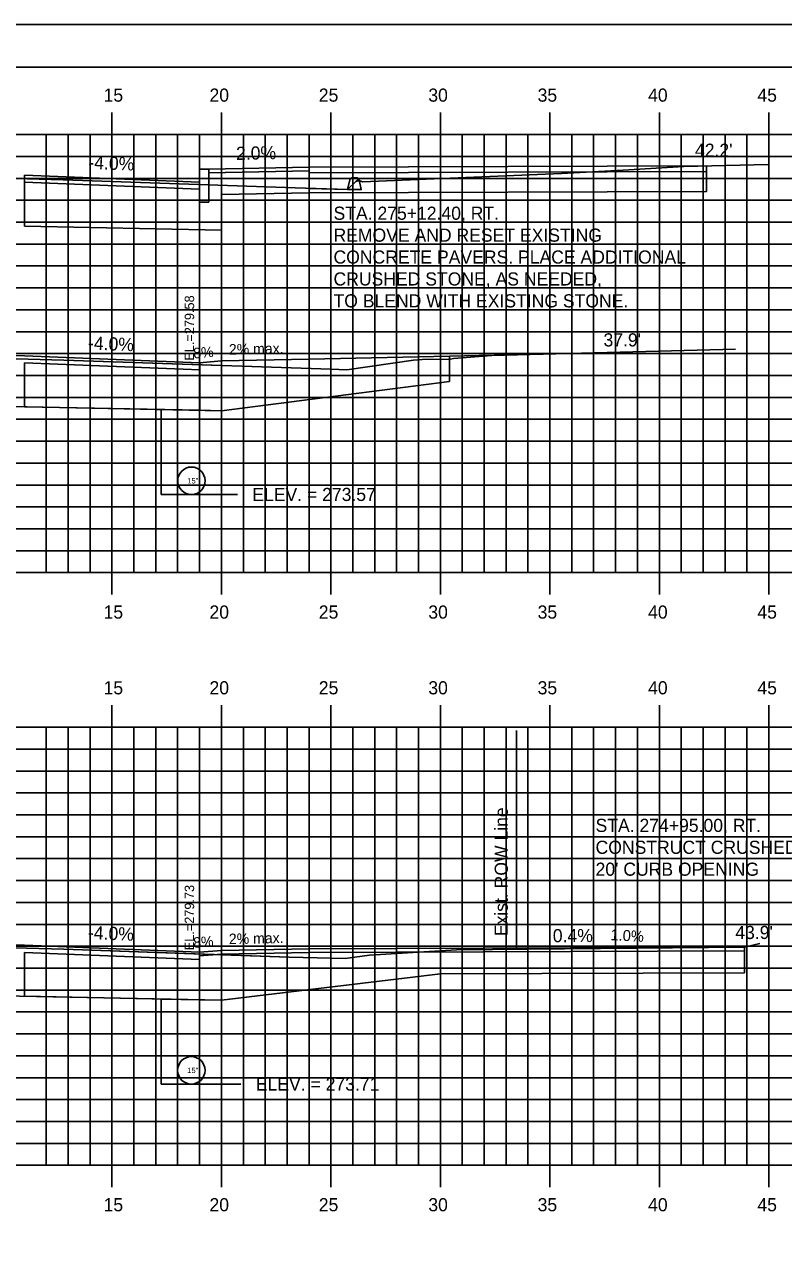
# Model space of a CAD drawing. Extents: x 853340 to 853510, y 366268 to 366378.
# Drawn here: x 853434.1 to 853468.8, y 366322.1 to 366378.2 of the extents above; entities that cross this region are included whole.
import ezdxf

# ---------------------------------------------------------------- set-up
doc = ezdxf.new("R2010")
doc.units = 0
for name, color, linetype in [('ANNOTATION', 7, 'Continuous'), ('BORDER', 7, 'Continuous'), ('D_Curb_Type_1_Rt', 7, 'Continuous'), ('D_Roadway_Drive_Gravel_RT', 7, 'Continuous'), ('D_Roadway_Drive_SubGrade', 7, 'Continuous'), ('D_Roadway_Edge_TW', 7, 'Continuous'), ('D_Roadway_Sidewalks_Paved', 7, 'Continuous'), ('D_Roadway_SubGrade', 7, 'Continuous'), ('D_Text_Monospaced', 7, 'Continuous'), ('D_Text_Standard', 7, 'Continuous'), ('E_ROW_Line', 7, 'Continuous'), ('H_V ANNOTATION', 7, 'Continuous'), ('JUNK COM EXC', 7, 'Continuous'), ('junk strct exc', 7, 'Continuous'), ('MAJOR', 7, 'Continuous'), ('MINOR', 7, 'Continuous'), ('PDRAIN', 7, 'Continuous'), ('PLOT BOUNDARY', 7, 'Continuous'), ('S_Curb_Type_3', 7, 'Continuous'), ('S_Roadway_Centerline', 7, 'Continuous')]:
    doc.layers.add(name, color=color, linetype=linetype)

msp = doc.modelspace()

# ---------------------------------------------------------------- linework, layer by layer
at = {"layer": 'BORDER'}
msp.add_line((853508.1, 366376.236), (853348.1, 366376.236), dxfattribs=at)
at = {"layer": 'D_Curb_Type_1_Rt'}
msp.add_lwpolyline([(853442.517, 366371.571), (853442.517, 366370.071), (853442.1, 366370.071), (853442.1, 366371.571)], close=True, dxfattribs=at)
at = {"layer": 'D_Roadway_Drive_Gravel_RT'}
for p, q in [((853442.1, 366362.74), (853443.1, 366362.82)), ((853442.107, 366362.407), (853442.107, 366362.74)), ((853443.1, 366362.82), (853447.1, 366362.9)), ((853442.099, 366335.825), (853443.099, 366335.905)), ((853442.1, 366333.653), (853442.1, 366335.826)), ((853442.1, 366335.658), (853443.108, 366335.739)), ((853443.099, 366335.905), (853447.099, 366335.985)), ((853443.108, 366335.739), (853447.103, 366335.819)), ((853466.982, 366336.058), (853447.099, 366335.985)), ((853447.099, 366335.985), (853447.099, 366335.985)), ((853466.982, 366335.891), (853447.1, 366335.819)), ((853466.982, 366334.891), (853453.1, 366334.841))]:
    msp.add_line(p, q, dxfattribs=at)
msp.add_lwpolyline([(853447.1, 366362.9), (853453.512, 366363.045), (853461.011, 366363.208)], dxfattribs=at)
at = {"layer": 'D_Roadway_Drive_SubGrade'}
for p, q in [((853453.512, 366361.879), (853453.512, 366363.045)), ((853443.101, 366360.548), (853453.512, 366361.879)), ((853442.101, 366360.568), (853443.101, 366360.548)), ((853466.982, 366336.058), (853466.982, 366334.891)), ((853443.1, 366333.633), (853453.1, 366334.841)), ((853442.1, 366333.653), (853443.1, 366333.633))]:
    msp.add_line(p, q, dxfattribs=at)
at = {"layer": 'D_Roadway_Edge_TW'}
for points in [[(853434.108, 366371.307), (853442.1, 366370.987)], [(853404.1, 366362.952), (853412.1, 366363.272), (853423.1, 366363.28), (853434.1, 366363.06), (853442.1, 366362.74)], [(853404.1, 366336.023), (853412.1, 366336.343), (853423.1, 366336.366), (853434.1, 366336.146), (853442.099, 366335.825)]]:
    msp.add_lwpolyline(points, dxfattribs=at)
at = {"layer": 'D_Roadway_Sidewalks_Paved'}
for p, q in [((853447.105, 366371.662), (853465.25, 366371.721)), ((853447.1, 366371.412), (853465.25, 366371.471))]:
    msp.add_line(p, q, dxfattribs=at)
msp.add_lwpolyline([(853442.517, 366371.571), (853447.105, 366371.662), (853447.105, 366371.496), (853442.517, 366371.404)], close=True, dxfattribs=at)
at = {"layer": 'D_Roadway_SubGrade'}
for p, q in [((853465.25, 366370.554), (853465.25, 366371.721)), ((853434.108, 366370.975), (853434.108, 366371.307)), ((853447.1, 366370.495), (853465.25, 366370.554))]:
    msp.add_line(p, q, dxfattribs=at)
for points in [[(853443.1, 366368.795), (853434.108, 366368.975), (853434.108, 366370.975), (853442.1, 366370.655)], [(853442.516, 366371.404), (853447.105, 366371.496), (853447.105, 366370.496), (853443.1, 366370.415), (853443.1, 366368.795)], [(853442.107, 366360.567), (853434.107, 366360.727), (853434.107, 366362.727), (853442.107, 366362.407), (853442.107, 366360.567)], [(853442.1, 366333.653), (853434.107, 366333.813), (853434.107, 366335.813), (853442.1, 366335.493)]]:
    msp.add_lwpolyline(points, dxfattribs=at)
at = {"layer": 'D_Text_Standard'}
for points in [[(853443.101, 366356.726), (853443.149, 366356.726), (853443.829, 366356.726)], [(853443.1, 366329.809), (853443.31, 366329.809), (853443.99, 366329.809)]]:
    msp.add_lwpolyline(points, dxfattribs=at)
at = {"layer": 'E_ROW_Line'}
msp.add_line((853456.579, 366335.956), (853456.579, 366345.956), dxfattribs=at)
at = {"layer": 'JUNK COM EXC'}
for points in [[(853447.101, 366370.699), (853447.1, 366370.495), (853465.25, 366370.554), (853465.25, 366371.721), (853464.215, 366371.694), (853461.455, 366371.527), (853458.624, 366371.375), (853449.544, 366370.995), (853449.384, 366371.065), (853449.231, 366371.012), (853448.861, 366370.64), (853447.101, 366370.699)], [(853403.1, 366362.838), (853403.1, 366360.759), (853412.107, 366360.939), (853423.107, 366360.947), (853443.101, 366360.548), (853443.1, 366362.612), (853435.895, 366362.863), (853428.824, 366363.051), (853423.1, 366363.253), (853411.854, 366363.201), (853411.562, 366363.195), (853404.759, 366362.908), (853404.544, 366362.894), (853403.28, 366362.845), (853403.1, 366362.838)], [(853403.1, 366335.883), (853403.1, 366333.83), (853412.107, 366334.01), (853423.107, 366334.033), (853443.1, 366333.633), (853443.1, 366335.711), (853435.908, 366335.962), (853427.945, 366336.173), (853423.1, 366336.344), (853413.581, 366336.299), (853411.556, 366336.262), (853405.802, 366336.019), (853404.553, 366335.94), (853403.1, 366335.883)], [(853466.982, 366334.891), (853466.982, 366336.058), (853453.832, 366335.929), (853449.861, 366335.698), (853448.746, 366335.536), (853446.195, 366335.603), (853443.1, 366335.711), (853443.1, 366333.633), (853453.1, 366334.841), (853466.982, 366334.891)]]:
    msp.add_lwpolyline(points, dxfattribs=at)
at = {"layer": 'junk strct exc'}
for points in [[(853440.351, 366360.602), (853440.351, 366356.726), (853443.101, 366356.726), (853443.101, 366360.548)], [(853440.35, 366333.688), (853440.35, 366329.809), (853443.1, 366329.809), (853443.1, 366333.633)]]:
    msp.add_lwpolyline(points, close=True, dxfattribs=at)
at = {"layer": 'MAJOR'}
for p, q in [((853438.1, 366374.158), (853438.1, 366373.156)), ((853443.1, 366374.158), (853443.1, 366373.156)), ((853448.1, 366374.158), (853448.1, 366373.156)), ((853453.1, 366374.158), (853453.1, 366373.156)), ((853458.1, 366374.158), (853458.1, 366373.156)), ((853463.1, 366374.158), (853463.1, 366373.156)), ((853468.1, 366374.158), (853468.1, 366373.156)), ((853353.1, 366373.156), (853493.1, 366373.156)), ((853353.1, 366373.156), (853493.1, 366373.156)), ((853438.1, 366353.156), (853438.1, 366373.156)), ((853443.1, 366353.156), (853443.1, 366373.156)), ((853448.1, 366353.156), (853448.1, 366373.156)), ((853453.1, 366353.156), (853453.1, 366373.156)), ((853458.1, 366353.156), (853458.1, 366373.156)), ((853463.1, 366353.156), (853463.1, 366373.156)), ((853468.1, 366353.156), (853468.1, 366373.156)), ((853353.1, 366368.156), (853493.1, 366368.156)), ((853353.1, 366363.156), (853493.1, 366363.156)), ((853353.1, 366358.156), (853493.1, 366358.156)), ((853353.1, 366353.156), (853493.1, 366353.156)), ((853353.1, 366353.156), (853493.1, 366353.156)), ((853438.1, 366352.154), (853438.1, 366353.156)), ((853443.1, 366352.154), (853443.1, 366353.156)), ((853448.1, 366352.154), (853448.1, 366353.156)), ((853453.1, 366352.154), (853453.1, 366353.156)), ((853458.1, 366352.154), (853458.1, 366353.156)), ((853463.1, 366352.154), (853463.1, 366353.156)), ((853468.1, 366352.154), (853468.1, 366353.156)), ((853438.1, 366347.101), (853438.1, 366346.099)), ((853443.1, 366347.101), (853443.1, 366346.099)), ((853448.1, 366347.101), (853448.1, 366346.099)), ((853453.1, 366347.101), (853453.1, 366346.099)), ((853458.1, 366347.101), (853458.1, 366346.099)), ((853463.1, 366347.101), (853463.1, 366346.099)), ((853468.1, 366347.101), (853468.1, 366346.099)), ((853353.1, 366346.099), (853493.1, 366346.099)), ((853353.1, 366346.099), (853493.1, 366346.099)), ((853438.1, 366326.099), (853438.1, 366346.099)), ((853443.1, 366326.099), (853443.1, 366346.099)), ((853448.1, 366326.099), (853448.1, 366346.099)), ((853453.1, 366326.099), (853453.1, 366346.099)), ((853458.1, 366326.099), (853458.1, 366346.099)), ((853463.1, 366326.099), (853463.1, 366346.099)), ((853468.1, 366326.099), (853468.1, 366346.099)), ((853353.1, 366341.099), (853493.1, 366341.099)), ((853353.1, 366336.099), (853493.1, 366336.099)), ((853353.1, 366331.099), (853493.1, 366331.099)), ((853353.1, 366326.099), (853493.1, 366326.099)), ((853353.1, 366326.099), (853493.1, 366326.099)), ((853438.1, 366325.097), (853438.1, 366326.099)), ((853443.1, 366325.097), (853443.1, 366326.099)), ((853448.1, 366325.097), (853448.1, 366326.099)), ((853453.1, 366325.097), (853453.1, 366326.099)), ((853458.1, 366325.097), (853458.1, 366326.099)), ((853463.1, 366325.097), (853463.1, 366326.099)), ((853468.1, 366325.097), (853468.1, 366326.099))]:
    msp.add_line(p, q, dxfattribs=at)
at = {"layer": 'MINOR'}
for p, q in [((853435.1, 366353.156), (853435.1, 366373.156)), ((853436.1, 366353.156), (853436.1, 366373.156)), ((853437.1, 366353.156), (853437.1, 366373.156)), ((853439.1, 366353.156), (853439.1, 366373.156)), ((853440.1, 366353.156), (853440.1, 366373.156)), ((853441.1, 366353.156), (853441.1, 366373.156)), ((853442.1, 366353.156), (853442.1, 366373.156)), ((853444.1, 366353.156), (853444.1, 366373.156)), ((853445.1, 366353.156), (853445.1, 366373.156)), ((853446.1, 366353.156), (853446.1, 366373.156)), ((853447.1, 366353.156), (853447.1, 366373.156)), ((853449.1, 366353.156), (853449.1, 366373.156)), ((853450.1, 366353.156), (853450.1, 366373.156)), ((853451.1, 366353.156), (853451.1, 366373.156)), ((853452.1, 366353.156), (853452.1, 366373.156)), ((853454.1, 366353.156), (853454.1, 366373.156)), ((853455.1, 366353.156), (853455.1, 366373.156)), ((853456.1, 366353.156), (853456.1, 366373.156)), ((853457.1, 366353.156), (853457.1, 366373.156)), ((853459.1, 366353.156), (853459.1, 366373.156)), ((853460.1, 366353.156), (853460.1, 366373.156)), ((853461.1, 366353.156), (853461.1, 366373.156)), ((853462.1, 366353.156), (853462.1, 366373.156)), ((853464.1, 366353.156), (853464.1, 366373.156)), ((853465.1, 366353.156), (853465.1, 366373.156)), ((853466.1, 366353.156), (853466.1, 366373.156)), ((853467.1, 366353.156), (853467.1, 366373.156)), ((853353.1, 366372.156), (853493.1, 366372.156)), ((853353.1, 366371.156), (853493.1, 366371.156)), ((853353.1, 366370.156), (853493.1, 366370.156)), ((853353.1, 366369.156), (853493.1, 366369.156)), ((853353.1, 366367.156), (853493.1, 366367.156)), ((853353.1, 366366.156), (853493.1, 366366.156)), ((853353.1, 366365.156), (853493.1, 366365.156)), ((853353.1, 366364.156), (853493.1, 366364.156)), ((853353.1, 366362.156), (853493.1, 366362.156)), ((853353.1, 366361.156), (853493.1, 366361.156)), ((853353.1, 366360.156), (853493.1, 366360.156)), ((853353.1, 366359.156), (853493.1, 366359.156)), ((853353.1, 366357.156), (853493.1, 366357.156)), ((853353.1, 366356.156), (853493.1, 366356.156)), ((853353.1, 366355.156), (853493.1, 366355.156)), ((853353.1, 366354.156), (853493.1, 366354.156)), ((853435.1, 366326.099), (853435.1, 366346.099)), ((853436.1, 366326.099), (853436.1, 366346.099)), ((853437.1, 366326.099), (853437.1, 366346.099)), ((853439.1, 366326.099), (853439.1, 366346.099)), ((853440.1, 366326.099), (853440.1, 366346.099)), ((853441.1, 366326.099), (853441.1, 366346.099)), ((853442.1, 366326.099), (853442.1, 366346.099)), ((853444.1, 366326.099), (853444.1, 366346.099)), ((853445.1, 366326.099), (853445.1, 366346.099)), ((853446.1, 366326.099), (853446.1, 366346.099)), ((853447.1, 366326.099), (853447.1, 366346.099)), ((853449.1, 366326.099), (853449.1, 366346.099)), ((853450.1, 366326.099), (853450.1, 366346.099)), ((853451.1, 366326.099), (853451.1, 366346.099)), ((853452.1, 366326.099), (853452.1, 366346.099)), ((853454.1, 366326.099), (853454.1, 366346.099)), ((853455.1, 366326.099), (853455.1, 366346.099)), ((853456.1, 366326.099), (853456.1, 366346.099)), ((853457.1, 366326.099), (853457.1, 366346.099)), ((853459.1, 366326.099), (853459.1, 366346.099)), ((853460.1, 366326.099), (853460.1, 366346.099)), ((853461.1, 366326.099), (853461.1, 366346.099)), ((853462.1, 366326.099), (853462.1, 366346.099)), ((853464.1, 366326.099), (853464.1, 366346.099)), ((853465.1, 366326.099), (853465.1, 366346.099)), ((853466.1, 366326.099), (853466.1, 366346.099)), ((853467.1, 366326.099), (853467.1, 366346.099)), ((853353.1, 366345.099), (853493.1, 366345.099)), ((853353.1, 366344.099), (853493.1, 366344.099)), ((853353.1, 366343.099), (853493.1, 366343.099)), ((853353.1, 366342.099), (853493.1, 366342.099)), ((853353.1, 366340.099), (853493.1, 366340.099)), ((853353.1, 366339.099), (853493.1, 366339.099)), ((853353.1, 366338.099), (853493.1, 366338.099)), ((853353.1, 366337.099), (853493.1, 366337.099)), ((853353.1, 366335.099), (853493.1, 366335.099)), ((853353.1, 366334.099), (853493.1, 366334.099)), ((853353.1, 366333.099), (853493.1, 366333.099)), ((853353.1, 366332.099), (853493.1, 366332.099)), ((853353.1, 366330.099), (853493.1, 366330.099)), ((853353.1, 366329.099), (853493.1, 366329.099)), ((853353.1, 366328.099), (853493.1, 366328.099)), ((853353.1, 366327.099), (853493.1, 366327.099))]:
    msp.add_line(p, q, dxfattribs=at)
at = {"layer": 'PDRAIN'}
for points in [[(853440.351, 366360.602), (853440.351, 366356.726), (853443.101, 366356.726), (853443.101, 366360.548)], [(853440.35, 366333.688), (853440.35, 366329.809), (853443.1, 366329.809), (853443.1, 366333.633)]]:
    msp.add_lwpolyline(points, dxfattribs=at)
for centre in [(853441.726, 366357.351), (853441.725, 366330.434)]:
    msp.add_circle(centre, 0.625, dxfattribs=at)
at = {"layer": 'PLOT BOUNDARY'}
msp.add_lwpolyline([(853340.007, 366268.177), (853510.007, 366268.177), (853510.007, 366378.177), (853340.007, 366378.177)], close=True, dxfattribs=at)
at = {"layer": 'S_Curb_Type_3'}
for points in [[(853449.383, 366371.084), (853449.486, 366370.64), (853448.861, 366370.64), (853448.963, 366371.084)], [(853449.085, 366371.181), (853449.261, 366371.181)]]:
    msp.add_lwpolyline(points, dxfattribs=at)
for centre, start, end in [((853449.085, 366371.056), 90, 167.0054), ((853449.261, 366371.056), 12.9946, 90)]:
    msp.add_arc(centre, 0.125, start, end, dxfattribs=at)
at = {"layer": 'S_Roadway_Centerline'}
for points in [[(853423.1, 366371.492), (853430.382, 366371.235), (853435.872, 366371.089), (853446.468, 366370.72), (853448.861, 366370.64), (853449.231, 366371.012), (853449.329, 366371.104), (853449.384, 366371.065), (853449.544, 366370.995), (853458.624, 366371.375), (853461.455, 366371.527), (853464.215, 366371.694), (853468.073, 366371.793)], [(853379.745, 366362.132), (853396.858, 366362.243), (853400.236, 366362.728), (853403.28, 366362.845), (853404.544, 366362.894), (853404.759, 366362.908), (853411.562, 366363.195), (853411.854, 366363.201), (853423.1, 366363.253), (853428.824, 366363.051), (853435.895, 366362.863), (853448.102, 366362.438), (853448.825, 366362.419), (853451.873, 366362.862), (853452.264, 366362.884), (853453.558, 366362.897), (853453.702, 366362.932), (853455.448, 366363.065), (853466.573, 366363.351)], [(853397.921, 366335.625), (853399.647, 366335.648), (853400.667, 366335.788), (853404.553, 366335.94), (853405.802, 366336.019), (853411.556, 366336.262), (853413.581, 366336.299), (853423.1, 366336.344), (853427.945, 366336.173), (853435.908, 366335.962), (853446.195, 366335.603), (853448.746, 366335.536), (853449.861, 366335.698), (853453.832, 366335.929), (853466.982, 366336.058), (853467.693, 366336.23)]]:
    msp.add_lwpolyline(points, dxfattribs=at)

# ---------------------------------------------------------------- texts
at = {"layer": 'ANNOTATION'}
for s, rotation, p in [('-4.0%', 357.7095, (853437.014, 366371.592)), ('2.0%', 1.1363, (853443.773, 366371.996)), ('-4.0%', 357.7094, (853436.997, 366363.345)), ('-4.0%', 357.7092, (853436.995, 366336.43))]:
    msp.add_text(s, height=0.6, rotation=rotation, dxfattribs=at).set_placement(p)
for s, p in [('STA. 275+12.40, RT.', (853448.219, 366369.264)), ('REMOVE AND RESET EXISTING', (853448.219, 366368.264)), ('CONCRETE PAVERS. PLACE ADDITIONAL', (853448.219, 366367.264)), ('CRUSHED STONE, AS NEEDED,', (853448.219, 366366.264)), ('TO BLEND WITH EXISTING STONE.', (853448.219, 366365.264)), ('STA. 274+95.00, RT.', (853460.187, 366341.317)), ('CONSTRUCT CRUSHED STONE ENTRANCE', (853460.187, 366340.317)), ("20' CURB OPENING", (853460.187, 366339.317))]:
    msp.add_text(s, height=0.6, dxfattribs=at).set_placement(p)
at = {"layer": 'D_Roadway_Drive_Gravel_RT'}
for s, height, rotation, p in [('8%', 0.48, 4.5739, (853441.832, 366362.933)), ('2% max.', 0.48, 1.1922, (853443.445, 366363.107)), ('0.4%', 0.6, 0.2077, (853458.235, 366336.282)), ('8%', 0.48, 4.5739, (853441.831, 366336.019)), ('2% max.', 0.48, 1.1922, (853443.444, 366336.193))]:
    msp.add_text(s, height=height, rotation=rotation, dxfattribs=at).set_placement(p)
at = {"layer": 'D_Text_Monospaced'}
msp.add_text('1.0%', height=0.5, rotation=356.7808, dxfattribs=at).set_placement((853460.858, 366336.38))
at = {"layer": 'D_Text_Standard'}
for s, p in [("42.2'", (853464.728, 366372.14)), ("37.9'", (853460.55, 366363.482)), ('ELEV. = 273.57', (853444.509, 366356.426)), ("43.9'", (853466.569, 366336.429)), ('ELEV. = 273.71', (853444.67, 366329.509))]:
    msp.add_text(s, height=0.6, dxfattribs=at).set_placement(p)
for s, p in [(' EL.=279.58', (853441.854, 366362.671)), (' EL.=279.73', (853441.854, 366335.757))]:
    msp.add_text(s, height=0.4335, rotation=90, dxfattribs=at).set_placement(p)
at = {"layer": 'E_ROW_Line'}
msp.add_text('Exist. ROW Line', height=0.6, rotation=90, dxfattribs=at).set_placement((853456.179, 366336.556))
at = {"layer": 'H_V ANNOTATION'}
for s, p in [('15', (853437.717, 366374.656)), ('20', (853442.554, 366374.656)), ('25', (853447.546, 366374.656)), ('30', (853452.548, 366374.656)), ('35', (853457.54, 366374.656)), ('40', (853462.586, 366374.656)), ('45', (853467.578, 366374.656)), ('15', (853437.717, 366351.056)), ('20', (853442.554, 366351.056)), ('25', (853447.546, 366351.056)), ('30', (853452.548, 366351.056)), ('35', (853457.54, 366351.056)), ('40', (853462.586, 366351.056)), ('45', (853467.578, 366351.056)), ('15', (853437.717, 366347.599)), ('20', (853442.554, 366347.599)), ('25', (853447.546, 366347.599)), ('30', (853452.548, 366347.599)), ('35', (853457.54, 366347.599)), ('40', (853462.586, 366347.599)), ('45', (853467.578, 366347.599)), ('15', (853437.717, 366323.999)), ('20', (853442.554, 366323.999)), ('25', (853447.546, 366323.999)), ('30', (853452.548, 366323.999)), ('35', (853457.54, 366323.999)), ('40', (853462.586, 366323.999)), ('45', (853467.578, 366323.999))]:
    msp.add_text(s, height=0.6, dxfattribs=at).set_placement(p)
at = {"layer": 'PDRAIN'}
for p in [(853441.539, 366357.226), (853441.538, 366330.309)]:
    msp.add_text('15"', height=0.25, dxfattribs=at).set_placement(p)

doc.saveas('drawing.dxf')
